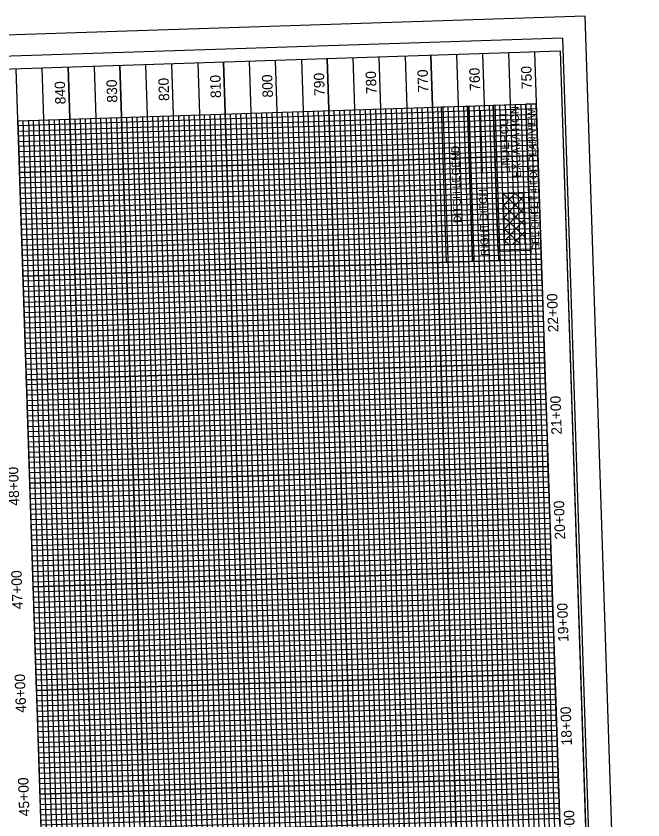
# Model space of a CAD drawing. Extents: x 1627318 to 1628473, y 762308 to 764226.
# Drawn here: x 1627868 to 1628473, y 763268 to 764043 of the extents above; entities that cross this region are included whole.
import ezdxf

# ---------------------------------------------------------------- set-up
doc = ezdxf.new("R2010")
doc.units = 0
for name, color, linetype in [('Exist Vertical Profile Horizontal Axis Label Major', 7, 'Continuous'), ('Exist Vertical Profile Vertical Axis Label', 7, 'Continuous'), ('Prop DSN Text', 7, 'Continuous'), ('Prop Grid Mask', 7, 'Continuous'), ('Prop PFL Ditch Label CELL', 7, 'Continuous'), ('Prop XS Undercut Exc Hatch', 7, 'Continuous'), ('Prop XSC Text', 7, 'Continuous'), ('Sheet DOT Grid CELL', 7, 'Continuous'), ('Sheet Layout Profile Border Port 2', 7, 'Continuous'), ('Sheet Plot Border Inside CELL', 7, 'Continuous'), ('Sheet Plot Border Outside CELL', 7, 'Continuous'), ('Sheet Profile CELL', 7, 'Continuous'), ('Sheet Profile Grid Major CELL', 7, 'Continuous'), ('Sheet Profile Grid Middle CELL', 7, 'Continuous'), ('Sheet Profile Grid Minor CELL', 7, 'Continuous')]:
    doc.layers.add(name, color=color, linetype=linetype)

msp = doc.modelspace()

# ---------------------------------------------------------------- linework, layer by layer
at = {"layer": 'Prop Grid Mask'}
for points in [[(1628283.19, 763805.99), (1628278.29, 763955.91), (1628303.27, 763956.73), (1628308.18, 763806.81)], [(1628308.18, 763806.81), (1628303.27, 763956.73), (1628328.26, 763957.54), (1628333.16, 763807.62)], [(1628332.88, 763816.37), (1628328.26, 763957.54), (1628359.71, 763958.57), (1628364.33, 763817.4)], [(1628359.71, 763958.57), (1628364.45, 763813.65), (1628374.45, 763813.98), (1628369.71, 763958.9)], [(1628358.93, 763823.74), (1628357.33, 763872.52), (1628337.61, 763871.87), (1628339.21, 763823.09)]]:
    msp.add_lwpolyline(points, close=True, dxfattribs=at)
at = {"layer": 'Prop PFL Ditch Label CELL'}
for p, q in [((1628318.02, 763892.73), (1628316.06, 763952.69)), ((1628318.02, 763892.73), (1628316.06, 763952.69)), ((1628323.17, 763807.3), (1628323.17, 763807.3))]:
    msp.add_line(p, q, dxfattribs=at)
at = {"layer": 'Prop XS Undercut Exc Hatch'}
for p, q in [((1628337.62, 763871.69), (1628337.79, 763871.88)), ((1628357.96, 763853.16), (1628337.97, 763871.89)), ((1628337.99, 763860.39), (1628349.1, 763872.25)), ((1628357.59, 763864.47), (1628349.28, 763872.26)), ((1628338.36, 763849.08), (1628357.43, 763869.44)), ((1628358.33, 763841.86), (1628337.97, 763860.93)), ((1628338.73, 763837.77), (1628357.8, 763858.14)), ((1628358.7, 763830.55), (1628338.34, 763849.62)), ((1628339.1, 763826.46), (1628358.17, 763846.83)), ((1628354.43, 763823.59), (1628338.71, 763838.32)), ((1628347.15, 763823.35), (1628358.54, 763835.52)), ((1628343.12, 763823.22), (1628339.08, 763827.01)), ((1628358.45, 763823.72), (1628358.91, 763824.21))]:
    msp.add_line(p, q, dxfattribs=at)
at = {"layer": 'Sheet DOT Grid CELL'}
for p, q in [((1628217.22, 762503.14), (1628168.18, 764002.22)), ((1628267.19, 762504.77), (1628218.15, 764003.86)), ((1628317.16, 762506.41), (1628268.13, 764005.49)), ((1628367.14, 762508.04), (1628318.1, 764007.13)), ((1628017.32, 762496.6), (1627968.29, 763995.68)), ((1628067.3, 762498.23), (1628018.26, 763997.32)), ((1628117.27, 762499.87), (1628068.23, 763998.95)), ((1628167.24, 762501.5), (1628118.21, 764000.59)), ((1627917.38, 762493.33), (1627868.34, 763992.41)), ((1627967.35, 762494.96), (1627918.31, 763994.05)), ((1627869.97, 763942.55), (1628369.71, 763958.9)), ((1627871.61, 763892.58), (1628371.34, 763908.93)), ((1627873.24, 763842.61), (1628372.97, 763858.95)), ((1627874.88, 763792.63), (1628374.61, 763808.98)), ((1627876.51, 763742.66), (1628376.24, 763759.01)), ((1627878.15, 763692.69), (1628377.88, 763709.03)), ((1627879.78, 763642.71), (1628379.51, 763659.06)), ((1627881.41, 763592.74), (1628381.15, 763609.09)), ((1627883.05, 763542.77), (1628382.78, 763559.11)), ((1627884.68, 763492.79), (1628384.42, 763509.14)), ((1627886.32, 763442.82), (1628386.05, 763459.17)), ((1627887.95, 763392.85), (1628387.69, 763409.19)), ((1627889.59, 763342.87), (1628389.32, 763359.22)), ((1627891.22, 763292.9), (1628390.96, 763309.25))]:
    msp.add_line(p, q, dxfattribs=at)
at = {"layer": 'Sheet Layout Profile Border Port 2'}
msp.add_lwpolyline([(1627915.74, 762543.3), (1627869.97, 763942.55), (1628369.71, 763958.9), (1628415.47, 762559.65)], close=True, dxfattribs=at)
at = {"layer": 'Sheet Plot Border Inside CELL'}
msp.add_lwpolyline([(1628449.68, 762356.66), (1628395.2, 764022.27), (1627340.66, 763987.77), (1627395.14, 762322.16)], close=True, dxfattribs=at)
at = {"layer": 'Sheet Plot Border Outside CELL'}
msp.add_lwpolyline([(1628472.54, 762344.4), (1628416.96, 764043.49), (1627317.55, 764007.53), (1627373.13, 762308.44)], close=True, dxfattribs=at)
at = {"layer": 'Sheet Profile CELL'}
for p, q in [((1628368.07, 764008.87), (1628417.11, 762509.68)), ((1628442.1, 762510.49), (1628393.06, 764009.69)), ((1627917.38, 762493.33), (1627868.34, 763992.53))]:
    msp.add_line(p, q, dxfattribs=at)
msp.add_lwpolyline([(1627343.62, 763975.36), (1627392.66, 762476.17), (1628442.1, 762510.49), (1628393.06, 764009.69)], close=True, dxfattribs=at)
at = {"layer": 'Sheet Profile Grid Major CELL'}
for p, q in [((1627871.61, 763892.58), (1627869.97, 763942.55)), ((1628371.34, 763908.93), (1628371.34, 763908.93)), ((1627874.88, 763792.63), (1627873.24, 763842.61)), ((1627878.15, 763692.69), (1627876.51, 763742.66)), ((1627881.41, 763592.74), (1627879.78, 763642.71)), ((1627884.68, 763492.79), (1627883.05, 763542.77)), ((1627887.95, 763392.85), (1627886.32, 763442.82)), ((1627891.22, 763292.9), (1627889.59, 763342.87))]:
    msp.add_line(p, q, dxfattribs=at)
for points in [[(1628168.18, 764002.33), (1628217.22, 762503.14), (1628267.19, 762504.77), (1628218.15, 764003.97)], [(1628268.12, 764005.6), (1628317.16, 762506.41), (1628317.16, 762506.41), (1628367.14, 762508.04), (1628318.1, 764007.24)], [(1628368.07, 764008.87), (1628417.11, 762509.68)], [(1627968.28, 763995.8), (1628017.32, 762496.6), (1628067.3, 762498.23), (1628018.26, 763997.43)], [(1628068.23, 763999.07), (1628117.27, 762499.87), (1628167.24, 762501.5), (1628118.2, 764000.7)], [(1627918.31, 763994.16), (1627967.35, 762494.96)], [(1628392.59, 763259.27), (1628390.96, 763309.25), (1627891.22, 763292.9), (1627889.59, 763342.87), (1628389.32, 763359.22), (1628387.69, 763409.19), (1627887.95, 763392.85), (1627886.32, 763442.82), (1628386.05, 763459.17), (1628384.42, 763509.14), (1627884.68, 763492.79), (1627883.05, 763542.77), (1628382.78, 763559.11), (1628381.15, 763609.09), (1627881.41, 763592.74), (1627879.78, 763642.71), (1628379.51, 763659.06), (1628377.88, 763709.03), (1627878.15, 763692.69), (1627876.51, 763742.66), (1628376.24, 763759.01), (1628374.61, 763808.98), (1627874.88, 763792.63), (1627873.24, 763842.61), (1628372.97, 763858.95), (1628371.34, 763908.93), (1628371.34, 763908.93), (1627871.61, 763892.58), (1627869.97, 763942.55), (1628369.71, 763958.9)]]:
    msp.add_lwpolyline(points, dxfattribs=at)
at = {"layer": 'Sheet Profile Grid Middle CELL'}
for points in [[(1628143.19, 764001.52), (1628192.23, 762502.32), (1628242.2, 762503.95), (1628193.16, 764003.15)], [(1628243.14, 764004.79), (1628292.18, 762505.59), (1628342.15, 762507.22), (1628293.11, 764006.42)], [(1628343.08, 764008.06), (1628392.12, 762508.86)], [(1627943.3, 763994.98), (1627992.34, 762495.78), (1628042.31, 762497.42), (1627993.27, 763996.61)], [(1628043.24, 763998.25), (1628092.28, 762499.05), (1628142.26, 762500.68), (1628093.22, 763999.88)], [(1627942.36, 762494.15), (1627893.32, 763993.34)], [(1627892.04, 763267.91), (1628391.77, 763284.26), (1628390.14, 763334.23), (1627890.41, 763317.89), (1627888.77, 763367.86), (1628388.5, 763384.21), (1628386.87, 763434.18), (1627887.14, 763417.83), (1627885.5, 763467.81), (1628385.23, 763484.15), (1628383.6, 763534.13), (1627883.87, 763517.78), (1627882.23, 763567.75), (1628381.96, 763584.1), (1628380.33, 763634.07), (1627880.6, 763617.73), (1627878.96, 763667.7), (1628378.7, 763684.05), (1628377.06, 763734.02), (1627877.33, 763717.67), (1627875.69, 763767.65), (1628375.43, 763783.99), (1628373.79, 763833.97), (1627874.06, 763817.62), (1627872.42, 763867.59), (1628372.16, 763883.94), (1628370.52, 763933.91), (1627870.79, 763917.57)]]:
    msp.add_lwpolyline(points, dxfattribs=at)
at = {"layer": 'Sheet Profile Grid Minor CELL'}
for p, q in [((1628264.76, 763955.47), (1628310.53, 762556.22)), ((1628320.53, 762556.54), (1628274.76, 763955.79)), ((1628279.75, 763955.96), (1628325.52, 762556.71)), ((1628330.52, 762556.87), (1628284.75, 763956.12)), ((1628289.75, 763956.28), (1628335.52, 762557.03)), ((1628345.51, 762557.36), (1628299.74, 763956.61)), ((1628304.74, 763956.78), (1628350.51, 762557.52)), ((1628355.51, 762557.69), (1628309.74, 763956.94)), ((1628314.73, 763957.1), (1628360.5, 762557.85)), ((1628370.5, 762558.18), (1628324.73, 763957.43)), ((1628329.73, 763957.59), (1628375.5, 762558.34)), ((1628380.49, 762558.5), (1628334.72, 763957.76)), ((1628339.72, 763957.92), (1628385.49, 762558.67)), ((1628395.49, 762558.99), (1628349.72, 763958.25)), ((1628354.71, 763958.41), (1628400.48, 762559.16)), ((1628405.48, 762559.32), (1628359.71, 763958.57)), ((1628364.71, 763958.74), (1628364.71, 763958.74)), ((1628410.48, 762559.49), (1628364.71, 763958.74)), ((1628029.89, 763947.78), (1628075.66, 762548.53)), ((1628080.65, 762548.7), (1628034.88, 763947.95)), ((1628039.88, 763948.11), (1628085.65, 762548.86)), ((1628095.65, 762549.19), (1628049.88, 763948.44)), ((1628054.87, 763948.6), (1628100.64, 762549.35)), ((1628105.64, 762549.51), (1628059.87, 763948.77)), ((1628064.87, 763948.93), (1628110.49, 762549.67)), ((1628120.63, 762550), (1628074.86, 763949.26)), ((1628079.86, 763949.42), (1628125.63, 762550.17)), ((1628130.63, 762550.33), (1628084.86, 763949.58)), ((1628089.85, 763949.75), (1628135.62, 762550.49)), ((1628145.62, 762550.82), (1628099.85, 763950.07)), ((1628104.85, 763950.24), (1628150.62, 762550.99)), ((1628155.61, 762551.15), (1628109.84, 763950.4)), ((1628114.84, 763950.56), (1628160.61, 762551.31)), ((1628170.61, 762551.64), (1628124.84, 763950.89)), ((1628129.83, 763951.05), (1628175.6, 762551.8)), ((1628180.6, 762551.97), (1628134.83, 763951.22)), ((1628139.83, 763951.38), (1628185.6, 762552.13)), ((1628195.59, 762552.46), (1628149.82, 763951.71)), ((1628154.82, 763951.87), (1628200.59, 762552.62)), ((1628205.59, 762552.78), (1628159.82, 763952.03)), ((1628164.81, 763952.2), (1628210.58, 762552.95)), ((1628220.58, 762553.27), (1628174.81, 763952.53)), ((1628179.81, 763952.69), (1628225.58, 762553.44)), ((1628230.57, 762553.6), (1628184.8, 763952.85)), ((1628189.8, 763953.02), (1628235.57, 762553.76)), ((1628245.57, 762554.09), (1628199.8, 763953.34)), ((1628204.79, 763953.51), (1628250.56, 762554.25)), ((1628255.56, 762554.42), (1628209.79, 763953.67)), ((1628214.79, 763953.83), (1628260.56, 762554.58)), ((1628270.55, 762554.91), (1628224.78, 763954.16)), ((1628229.78, 763954.32), (1628275.55, 762555.07)), ((1628280.55, 762555.24), (1628234.78, 763954.49)), ((1628239.77, 763954.65), (1628285.54, 762555.4)), ((1628295.54, 762555.73), (1628249.77, 763954.98)), ((1628254.77, 763955.14), (1628300.54, 762555.89)), ((1628305.53, 762556.05), (1628259.76, 763955.3)), ((1627920.74, 762543.47), (1627874.97, 763942.72)), ((1627879.97, 763942.88), (1627925.74, 762543.63)), ((1627930.73, 762543.79), (1627884.96, 763943.04)), ((1627889.96, 763943.21), (1627935.73, 762543.96)), ((1627945.73, 762544.28), (1627899.96, 763943.53)), ((1627904.95, 763943.7), (1627950.72, 762544.45)), ((1627955.72, 762544.61), (1627909.95, 763943.86)), ((1627914.95, 763944.03), (1627960.72, 762544.77)), ((1627970.71, 762545.1), (1627924.94, 763944.35)), ((1627929.94, 763944.52), (1627975.71, 762545.26)), ((1627980.71, 762545.43), (1627934.94, 763944.68)), ((1627939.94, 763944.84), (1627985.7, 762545.59)), ((1627995.7, 762545.92), (1627949.93, 763945.17)), ((1627954.93, 763945.33), (1628000.7, 762546.08)), ((1628005.69, 762546.24), (1627959.92, 763945.5)), ((1627964.92, 763945.66), (1628010.69, 762546.41)), ((1628020.69, 762546.74), (1627974.92, 763945.99)), ((1627979.91, 763946.15), (1628025.68, 762546.9)), ((1628030.68, 762547.06), (1627984.91, 763946.31)), ((1627989.91, 763946.48), (1628035.68, 762547.23)), ((1628045.67, 762547.55), (1627999.9, 763946.8)), ((1628004.9, 763946.97), (1628050.67, 762547.72)), ((1628055.67, 762547.88), (1628009.9, 763947.13)), ((1628014.89, 763947.29), (1628060.66, 762548.04)), ((1628070.66, 762548.37), (1628024.89, 763947.62))]:
    msp.add_line(p, q, dxfattribs=at)
for points in [[(1628378.21, 763699.04), (1628378.04, 763704.04), (1627878.31, 763687.69), (1627877.98, 763697.68), (1628377.71, 763714.03), (1628377.55, 763719.03), (1627877.82, 763702.68), (1627877.66, 763707.68), (1628377.39, 763724.03), (1628377.22, 763729.02), (1627877.49, 763712.68), (1627877.16, 763722.67), (1628376.9, 763739.02), (1628376.73, 763744.02), (1627877, 763727.67), (1627876.84, 763732.67), (1628376.57, 763749.01), (1628376.41, 763754.01), (1627876.67, 763737.66), (1627876.35, 763747.66), (1628376.08, 763764), (1628375.92, 763769), (1627876.18, 763752.66), (1627876.02, 763757.65), (1628375.75, 763774), (1628375.59, 763779), (1627875.86, 763762.65), (1627875.53, 763772.64), (1628375.26, 763788.99), (1628375.1, 763793.99), (1627875.37, 763777.64), (1627875.2, 763782.64), (1628374.94, 763798.99), (1628374.77, 763803.98), (1627875.04, 763787.64), (1627874.71, 763797.63), (1628374.45, 763813.98), (1628374.28, 763818.98), (1627874.55, 763802.63), (1627874.39, 763807.63), (1628374.12, 763823.97), (1628373.96, 763828.97), (1627874.22, 763812.62), (1627873.9, 763822.62), (1628373.63, 763838.96), (1628373.46, 763843.96), (1627873.73, 763827.62), (1627873.57, 763832.61), (1628373.3, 763848.96), (1628373.14, 763853.96), (1627873.41, 763837.61), (1627873.08, 763847.6), (1628372.81, 763863.95), (1628372.65, 763868.95), (1627872.91, 763852.6), (1627872.75, 763857.6), (1628372.48, 763873.95), (1628372.32, 763878.94), (1627872.59, 763862.6), (1627872.26, 763872.59), (1628371.99, 763888.94), (1628371.83, 763893.93), (1627872.1, 763877.59), (1627871.93, 763882.59), (1628371.67, 763898.93), (1628371.5, 763903.93), (1627871.77, 763887.58), (1627871.44, 763897.58), (1628371.18, 763913.92), (1628371.01, 763918.92), (1627871.28, 763902.58), (1627871.12, 763907.57), (1628370.85, 763923.92), (1628370.69, 763928.92), (1627870.95, 763912.57), (1627870.63, 763922.56), (1628370.36, 763938.91), (1628370.2, 763943.91), (1627870.46, 763927.56), (1627870.3, 763932.56), (1628370.03, 763948.91), (1628369.87, 763953.9), (1627870.14, 763937.56), (1627869.97, 763942.55)], [(1628388.18, 763394.2), (1627888.44, 763377.86), (1627888.28, 763382.85), (1628388.01, 763399.2), (1628387.85, 763404.2), (1627888.12, 763387.85), (1627887.79, 763397.85), (1628387.52, 763414.19), (1628387.36, 763419.19), (1627887.63, 763402.84), (1627887.46, 763407.84), (1628387.2, 763424.19), (1628387.03, 763429.18), (1627887.3, 763412.84), (1627886.97, 763422.83), (1628386.71, 763439.18), (1628386.54, 763444.18), (1627886.81, 763427.83), (1627886.65, 763432.83), (1628386.38, 763449.17), (1628386.21, 763454.17), (1627886.48, 763437.82), (1627886.16, 763447.82), (1628385.89, 763464.16), (1628385.72, 763469.16), (1627885.99, 763452.82), (1627885.83, 763457.81), (1628385.56, 763474.16), (1628385.4, 763479.16), (1627885.66, 763462.81), (1627885.34, 763472.81), (1628385.07, 763489.15), (1628384.91, 763494.15), (1627885.17, 763477.8), (1627885.01, 763482.8), (1628384.74, 763499.15), (1628384.58, 763504.14), (1627884.85, 763487.8), (1627884.52, 763497.79), (1628384.25, 763514.14), (1628384.09, 763519.14), (1627884.36, 763502.79), (1627884.19, 763507.79), (1628383.93, 763524.13), (1628383.76, 763529.13), (1627884.03, 763512.78), (1627883.7, 763522.78), (1628383.44, 763539.12), (1628383.27, 763544.12), (1627883.54, 763527.78), (1627883.38, 763532.77), (1628383.11, 763549.12), (1628382.95, 763554.12), (1627883.21, 763537.77), (1627882.89, 763547.77), (1628382.62, 763564.11), (1628382.46, 763569.11), (1627882.72, 763552.76), (1627882.56, 763557.76), (1628382.29, 763574.11), (1628382.13, 763579.1), (1627882.4, 763562.76), (1627882.07, 763572.75), (1628381.8, 763589.1), (1628381.64, 763594.1), (1627881.91, 763577.75), (1627881.74, 763582.75), (1628381.47, 763599.09), (1628381.31, 763604.09), (1627881.58, 763587.74), (1627881.25, 763597.74), (1628380.98, 763614.08), (1628380.82, 763619.08), (1627881.09, 763602.74), (1627880.92, 763607.73), (1628380.66, 763624.08), (1628380.49, 763629.08), (1627880.76, 763612.73), (1627880.43, 763622.73), (1628380.17, 763639.07), (1628380, 763644.07), (1627880.27, 763627.72), (1627880.11, 763632.72), (1628379.84, 763649.07), (1628379.68, 763654.06), (1627879.94, 763637.72), (1627879.62, 763647.71), (1628379.35, 763664.06), (1628379.19, 763669.06), (1627879.45, 763652.71), (1627879.29, 763657.71), (1628379.02, 763674.05), (1628378.86, 763679.05), (1627879.13, 763662.7), (1627878.8, 763672.7), (1628378.53, 763689.04), (1628378.37, 763694.04), (1627878.64, 763677.7), (1627878.47, 763682.69), (1628378.21, 763699.04)], [(1627892.37, 763257.92), (1628392.1, 763274.27), (1628391.94, 763279.26), (1627892.2, 763262.92), (1627891.88, 763272.91), (1628391.61, 763289.26), (1628391.45, 763294.26), (1627891.71, 763277.91), (1627891.55, 763282.91), (1628391.28, 763299.25), (1628391.12, 763304.25), (1627891.39, 763287.9), (1627891.06, 763297.9), (1628390.79, 763314.24), (1628390.63, 763319.24), (1627890.9, 763302.9), (1627890.73, 763307.89), (1628390.46, 763324.24), (1628390.3, 763329.24), (1627890.57, 763312.89), (1627890.24, 763322.89), (1628389.97, 763339.23), (1628389.81, 763344.23), (1627890.08, 763327.88), (1627889.91, 763332.88), (1628389.65, 763349.23), (1628389.48, 763354.22), (1627889.75, 763337.88), (1627889.42, 763347.87), (1628389.16, 763364.22), (1628388.45, 763368.9), (1628388.99, 763369.22), (1627889.26, 763352.87), (1627889.1, 763357.87), (1628388.83, 763374.21), (1628388.67, 763379.21), (1627888.93, 763362.86), (1627888.61, 763372.86), (1628388.34, 763389.2), (1628388.18, 763394.2)], [(1628392.43, 763264.27), (1628392.26, 763269.27), (1627892.53, 763252.92)]]:
    msp.add_lwpolyline(points, dxfattribs=at)

# ---------------------------------------------------------------- texts
at = {"layer": 'Exist Vertical Profile Horizontal Axis Label Major'}
for s, p in [('22+00', (1628391.11, 763738.58)), ('21+00', (1628394.34, 763639.83)), ('48+00', (1627871.3, 763571.32)), ('20+00', (1628397.65, 763538.69)), ('47+00', (1627874.57, 763471.41)), ('19+00', (1628400.88, 763439.94)), ('46+00', (1627877.84, 763371.49)), ('18+00', (1628404.15, 763339.99)), ('45+00', (1627881.11, 763271.66)), ('17+00', (1628407.42, 763240.05))]:
    msp.add_text(s, height=10, rotation=91.87347, dxfattribs=at).set_placement(p)
at = {"layer": 'Exist Vertical Profile Vertical Axis Label'}
for s, p in [('750', (1628365.68, 763973.19)), ('800', (1628115.81, 763965.02)), ('790', (1628165.79, 763966.65)), ('780', (1628215.76, 763968.29)), ('770', (1628265.73, 763969.92)), ('760', (1628315.71, 763971.56)), ('840', (1627915.92, 763958.48)), ('830', (1627965.89, 763960.12)), ('820', (1628015.87, 763961.75)), ('810', (1628065.8, 763964.58))]:
    msp.add_text(s, height=10, rotation=91.87347, dxfattribs=at).set_placement(p)
at = {"layer": 'Prop DSN Text'}
msp.add_text('SEE SHEET 4 FOR PLAN VIEW', height=7, rotation=91.87347, dxfattribs=at).set_placement((1628372.74, 763817.7))
at = {"layer": 'Prop PFL Ditch Label CELL'}
for s, height, p in [('DITCH LEGEND', 7.5, (1628297.6, 763843.98)), ('RIGHT DITCH', 7.485, (1628323.9, 763812.32))]:
    msp.add_text(s, height=height, rotation=91.87347, dxfattribs=at).set_placement(p)
at = {"layer": 'Prop XSC Text'}
for s, p in [('EXCAVATION', (1628354.91, 763887.78)), ('UNDERCUT', (1628344.29, 763891.63))]:
    msp.add_text(s, height=8, rotation=91.87347, dxfattribs=at).set_placement(p)

doc.saveas('drawing.dxf')
